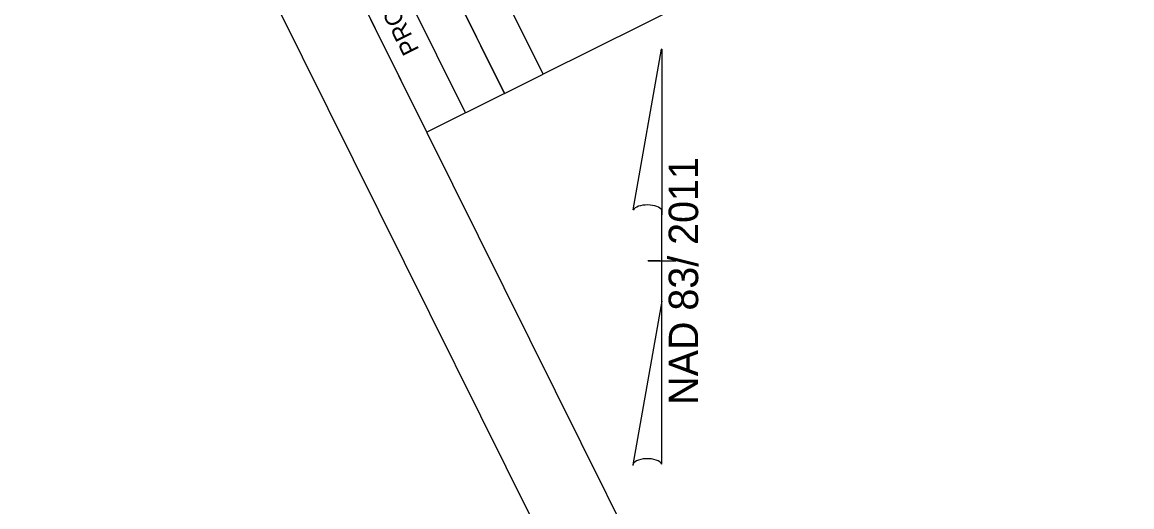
# Model space of a CAD drawing. Extents: x 475112 to 476842, y 500772 to 502767.
# Drawn here: x 475112 to 475432.3, y 501987 to 502126.7 of the extents above; entities that cross this region are included whole.
import ezdxf

# ---------------------------------------------------------------- set-up
doc = ezdxf.new("R2010")
doc.units = 0
for name, color, linetype in [('Prop North Arrow NAD83 for Plan Sheets CELL', 7, 'Continuous'), ('Sheet Plan CELL', 7, 'Continuous'), ('Sheet Plot Border Outside CELL', 7, 'Continuous')]:
    doc.layers.add(name, color=color, linetype=linetype)

msp = doc.modelspace()

# ---------------------------------------------------------------- linework, layer by layer
at = {"layer": 'Prop North Arrow NAD83 for Plan Sheets CELL'}
for p, q in [((475288.35, 502072.6), (475296.55, 502118.95)), ((475296.6, 502118.95), (475296.55, 502118.95)), ((475296.6, 502118.95), (475296.55, 502118.95)), ((475296.6, 502118.95), (475296.6, 502071.15)), ((475296.6, 502046.35), (475296.6, 502072.55)), ((475296.6, 502071.15), (475296.6, 502072.5)), ((475292.6, 502057.95), (475292.55, 502057.95)), ((475296.15, 502057.95), (475292.6, 502057.95)), ((475292.65, 502057.95), (475300.65, 502057.95)), ((475296.6, 502046.35), (475288.25, 501999.1)), ((475296.65, 501999.3), (475296.6, 502046.35))]:
    msp.add_line(p, q, dxfattribs=at)
for centre, start_param, end_param in [((475292.49, 502072.1), 0.216388, 2.908219), ((475292.49, 501998.93), 0.201328, 3.141593)]:
    msp.add_ellipse(centre, major_axis=(4.23, -0.03), ratio=0.461098, start_param=start_param, end_param=end_param, dxfattribs=at)
at = {"layer": 'Sheet Plan CELL'}
for p, q in [((475251.23, 502106.21), (475162.14, 502285.31)), ((475251.23, 502106.21), (475162.14, 502285.31)), ((475240.01, 502100.61), (475150.95, 502279.74)), ((475251.23, 502106.21), (475262.41, 502111.77))]:
    msp.add_line(p, q, dxfattribs=at)
for points in [[(475139.69, 502274.19), (475807.62, 500931.06), (476747.78, 501398.6), (476079.87, 502741.7)], [(475228.77, 502095.04), (475139.69, 502274.19), (475162.14, 502285.31), (475251.23, 502106.21)], [(475262.41, 502111.77), (475217.86, 502201.35), (475318.61, 502251.45), (475363.13, 502161.87)]]:
    msp.add_lwpolyline(points, close=True, dxfattribs=at)
at = {"layer": 'Sheet Plot Border Outside CELL'}
msp.add_lwpolyline([(476842.07, 501259.55), (476092.46, 502766.95), (475112, 502279.37), (475861.61, 500771.98)], close=True, dxfattribs=at)

# ---------------------------------------------------------------- texts
at = {"layer": 'Prop North Arrow NAD83 for Plan Sheets CELL'}
msp.add_text('NAD 83/ 2011', height=8.5, rotation=90, dxfattribs=at).set_placement((475307.12, 502016.43))
at = {"layer": 'Sheet Plan CELL'}
msp.add_text('PROJECT REFERENCE NO.', height=5.0001, rotation=116.4407, dxfattribs=at).set_placement((475226.7, 502118.8))

doc.saveas('drawing.dxf')
